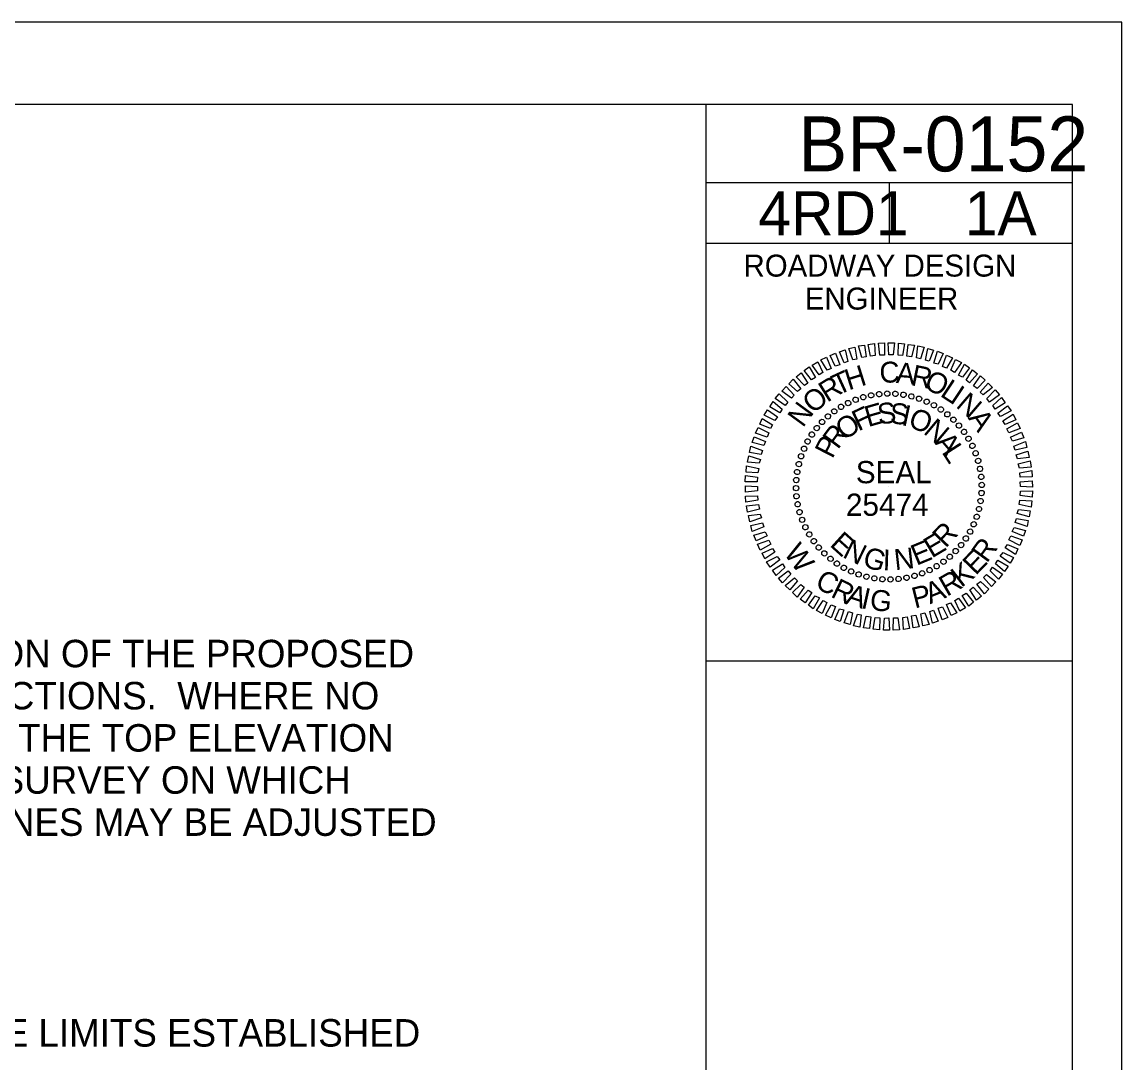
# Model space of a CAD drawing. Extents: x 1552903 to 1553045, y 811348 to 811440.
# Drawn here: x 1553019.79 to 1553044.82, y 811416.33 to 811440 of the extents above; entities that cross this region are included whole.
import ezdxf

# ---------------------------------------------------------------- set-up
doc = ezdxf.new("R2010")
doc.units = 0
for name, color, linetype in [('Default', 7, 'Continuous'), ('Prop Terminator CELL', 7, 'Continuous'), ('Sheet Data Field CELL', 7, 'Continuous'), ('Sheet Plan CELL', 7, 'Continuous'), ('Typical Grade Point Symbol CELL', 7, 'Continuous'), ('Typical Terminator CELL', 7, 'Continuous'), ('Typical Text General CELL', 7, 'Continuous'), ('z - Construction', 7, 'Continuous')]:
    doc.layers.add(name, color=color, linetype=linetype)

msp = doc.modelspace()

# ---------------------------------------------------------------- linework, layer by layer
at = {"layer": 'Prop Terminator CELL'}
for p, q in [((1553043.691, 811438.123), (1552906.191, 811438.123)), ((1553043.689, 811350.208), (1553043.691, 811438.123)), ((1553043.691, 811436.338), (1553035.358, 811436.338)), ((1553039.524, 811434.963), (1553039.524, 811436.338)), ((1553043.691, 811434.963), (1553035.358, 811434.963))]:
    msp.add_line(p, q, dxfattribs=at)
at = {"layer": 'Typical Grade Point Symbol CELL'}
for p, q in [((1553035.354, 811433.387), (1553035.354, 811433.387)), ((1553038.754, 811431.412), (1553038.754, 811431.412)), ((1553038.93, 811431.47), (1553038.93, 811431.47)), ((1553039.111, 811431.511), (1553039.111, 811431.511)), ((1553039.291, 811431.539), (1553039.291, 811431.539)), ((1553039.477, 811431.551), (1553039.477, 811431.551)), ((1553039.662, 811431.546), (1553039.662, 811431.546)), ((1553039.844, 811431.524), (1553039.844, 811431.524)), ((1553040.025, 811431.489), (1553040.025, 811431.489)), ((1553040.203, 811431.437), (1553040.203, 811431.437)), ((1553040.373, 811431.369), (1553040.373, 811431.369)), ((1553038.27, 811431.147), (1553038.27, 811431.147)), ((1553038.424, 811431.25), (1553038.424, 811431.25)), ((1553038.587, 811431.338), (1553038.587, 811431.338)), ((1553040.539, 811431.287), (1553040.539, 811431.287)), ((1553040.696, 811431.189), (1553040.696, 811431.189)), ((1553037.992, 811430.906), (1553037.992, 811430.906)), ((1553038.125, 811431.035), (1553038.125, 811431.035)), ((1553040.846, 811431.082), (1553040.846, 811431.082)), ((1553040.983, 811430.958), (1553040.983, 811430.958)), ((1553037.761, 811430.619), (1553037.761, 811430.619)), ((1553037.868, 811430.769), (1553037.868, 811430.769)), ((1553041.111, 811430.825), (1553041.111, 811430.825)), ((1553041.223, 811430.68), (1553041.223, 811430.68)), ((1553037.663, 811430.462), (1553037.663, 811430.462)), ((1553041.327, 811430.526), (1553041.327, 811430.526)), ((1553041.414, 811430.363), (1553041.414, 811430.363)), ((1553037.513, 811430.127), (1553037.513, 811430.127)), ((1553037.582, 811430.296), (1553037.582, 811430.296)), ((1553041.489, 811430.196), (1553041.489, 811430.196)), ((1553037.461, 811429.949), (1553037.461, 811429.949)), ((1553041.547, 811430.02), (1553041.547, 811430.02)), ((1553037.427, 811429.767), (1553037.427, 811429.767)), ((1553041.588, 811429.84), (1553041.588, 811429.84)), ((1553041.616, 811429.659), (1553041.616, 811429.659)), ((1553037.399, 811429.4), (1553037.399, 811429.4)), ((1553037.404, 811429.585), (1553037.404, 811429.585)), ((1553039.514, 811429.437), (1553039.514, 811429.437)), ((1553041.628, 811429.474), (1553041.628, 811429.474)), ((1553037.411, 811429.215), (1553037.411, 811429.215)), ((1553041.623, 811429.288), (1553041.623, 811429.288)), ((1553037.439, 811429.034), (1553037.439, 811429.034)), ((1553041.566, 811428.925), (1553041.566, 811428.925)), ((1553041.601, 811429.107), (1553041.601, 811429.107)), ((1553037.48, 811428.854), (1553037.48, 811428.854)), ((1553037.538, 811428.678), (1553037.538, 811428.678)), ((1553041.514, 811428.747), (1553041.514, 811428.747)), ((1553037.613, 811428.51), (1553037.613, 811428.51)), ((1553041.364, 811428.412), (1553041.364, 811428.412)), ((1553041.445, 811428.577), (1553041.445, 811428.577)), ((1553037.7, 811428.348), (1553037.7, 811428.348)), ((1553037.804, 811428.194), (1553037.804, 811428.194)), ((1553041.266, 811428.254), (1553041.266, 811428.254)), ((1553037.916, 811428.048), (1553037.916, 811428.048)), ((1553038.044, 811427.916), (1553038.044, 811427.916)), ((1553041.035, 811427.968), (1553041.035, 811427.968)), ((1553041.159, 811428.105), (1553041.159, 811428.105)), ((1553038.181, 811427.791), (1553038.181, 811427.791)), ((1553038.331, 811427.685), (1553038.331, 811427.685)), ((1553040.603, 811427.623), (1553040.603, 811427.623)), ((1553040.757, 811427.727), (1553040.757, 811427.727)), ((1553040.902, 811427.839), (1553040.902, 811427.839)), ((1553038.488, 811427.586), (1553038.488, 811427.586)), ((1553038.654, 811427.505), (1553038.654, 811427.505)), ((1553038.824, 811427.436), (1553038.824, 811427.436)), ((1553039.002, 811427.384), (1553039.002, 811427.384)), ((1553039.916, 811427.363), (1553039.916, 811427.363)), ((1553040.097, 811427.404), (1553040.097, 811427.404)), ((1553040.273, 811427.462), (1553040.273, 811427.462)), ((1553040.44, 811427.536), (1553040.44, 811427.536)), ((1553039.183, 811427.35), (1553039.183, 811427.35)), ((1553039.365, 811427.328), (1553039.365, 811427.328)), ((1553039.55, 811427.322), (1553039.55, 811427.322)), ((1553039.736, 811427.334), (1553039.736, 811427.334)), ((1553043.691, 811425.463), (1553043.691, 811425.463))]:
    msp.add_line(p, q, dxfattribs=at)
for points in [[(1553038.898, 811432.367), (1553038.822, 811432.631), (1553038.96, 811432.65), (1553038.999, 811432.381)], [(1553039.099, 811432.4), (1553039.044, 811432.664), (1553039.183, 811432.688), (1553039.2, 811432.414)], [(1553039.31, 811432.424), (1553039.275, 811432.698), (1553039.414, 811432.7), (1553039.411, 811432.426)], [(1553039.512, 811432.428), (1553039.499, 811432.702), (1553039.638, 811432.704), (1553039.613, 811432.43)], [(1553039.723, 811432.423), (1553039.73, 811432.697), (1553039.87, 811432.679), (1553039.824, 811432.412)], [(1553039.925, 811432.397), (1553039.954, 811432.667), (1553040.094, 811432.653), (1553040.027, 811432.386)], [(1553040.141, 811432.359), (1553040.174, 811432.633), (1553040.318, 811432.606), (1553040.23, 811432.339)], [(1553038.111, 811432.079), (1553037.968, 811432.313), (1553038.097, 811432.374), (1553038.203, 811432.123)], [(1553038.294, 811432.175), (1553038.177, 811432.417), (1553038.298, 811432.47), (1553038.395, 811432.206)], [(1553038.495, 811432.25), (1553038.39, 811432.501), (1553038.52, 811432.541), (1553038.583, 811432.281)], [(1553038.697, 811432.313), (1553038.599, 811432.576), (1553038.742, 811432.608), (1553038.785, 811432.335)], [(1553040.344, 811432.312), (1553040.398, 811432.574), (1553040.529, 811432.538), (1553040.433, 811432.284)], [(1553040.535, 811432.244), (1553040.623, 811432.511), (1553040.746, 811432.462), (1553040.636, 811432.216)], [(1553040.73, 811432.167), (1553040.826, 811432.421), (1553040.958, 811432.365), (1553040.823, 811432.126)], [(1553037.752, 811431.862), (1553037.589, 811432.07), (1553037.697, 811432.156), (1553037.844, 811431.914)], [(1553037.931, 811431.975), (1553037.767, 811432.195), (1553037.897, 811432.269), (1553038.011, 811432.027)], [(1553040.925, 811432.078), (1553041.03, 811432.324), (1553041.162, 811432.255), (1553041.006, 811432.029)], [(1553041.096, 811431.971), (1553041.234, 811432.218), (1553041.345, 811432.136), (1553041.189, 811431.922)], [(1553037.433, 811431.595), (1553037.24, 811431.773), (1553037.339, 811431.876), (1553037.512, 811431.656)], [(1553037.594, 811431.729), (1553037.406, 811431.928), (1553037.518, 811432.018), (1553037.673, 811431.789)], [(1553041.27, 811431.852), (1553041.418, 811432.086), (1553041.533, 811432), (1553041.351, 811431.795)], [(1553041.437, 811431.724), (1553041.601, 811431.95), (1553041.704, 811431.851), (1553041.518, 811431.667)], [(1553037.296, 811431.441), (1553037.078, 811431.606), (1553037.178, 811431.709), (1553037.362, 811431.51)], [(1553041.591, 811431.584), (1553041.769, 811431.789), (1553041.871, 811431.69), (1553041.659, 811431.518)], [(1553041.745, 811431.435), (1553041.931, 811431.632), (1553042.026, 811431.524), (1553041.806, 811431.356)], [(1553037.036, 811431.112), (1553036.802, 811431.247), (1553036.88, 811431.371), (1553037.086, 811431.193)], [(1553037.156, 811431.275), (1553036.93, 811431.435), (1553037.02, 811431.546), (1553037.213, 811431.356)], [(1553041.879, 811431.277), (1553042.078, 811431.462), (1553042.16, 811431.341), (1553041.931, 811431.198)], [(1553036.917, 811430.938), (1553036.675, 811431.056), (1553036.753, 811431.179), (1553036.979, 811431.019)], [(1553041.991, 811431.106), (1553042.212, 811431.274), (1553042.294, 811431.154), (1553042.056, 811431.027)], [(1553036.819, 811430.755), (1553036.578, 811430.852), (1553036.634, 811430.983), (1553036.869, 811430.836)], [(1553042.108, 811430.927), (1553042.337, 811431.083), (1553042.398, 811430.953), (1553042.16, 811430.848)], [(1553042.2, 811430.748), (1553042.442, 811430.882), (1553042.503, 811430.753), (1553042.243, 811430.656)], [(1553036.743, 811430.56), (1553036.48, 811430.648), (1553036.537, 811430.779), (1553036.783, 811430.653)], [(1553042.283, 811430.555), (1553042.534, 811430.673), (1553042.587, 811430.544), (1553042.327, 811430.468)], [(1553036.666, 811430.369), (1553036.404, 811430.436), (1553036.452, 811430.567), (1553036.707, 811430.458)], [(1553042.358, 811430.354), (1553042.622, 811430.46), (1553042.654, 811430.322), (1553042.389, 811430.266)], [(1553036.564, 811429.963), (1553036.298, 811429.987), (1553036.325, 811430.131), (1553036.592, 811430.051)], [(1553036.611, 811430.166), (1553036.344, 811430.211), (1553036.371, 811430.351), (1553036.639, 811430.254)], [(1553042.412, 811430.153), (1553042.676, 811430.242), (1553042.708, 811430.099), (1553042.443, 811430.065)], [(1553036.534, 811429.747), (1553036.264, 811429.763), (1553036.278, 811429.907), (1553036.553, 811429.849)], [(1553042.458, 811429.952), (1553042.73, 811430.02), (1553042.75, 811429.877), (1553042.481, 811429.851)], [(1553036.52, 811429.545), (1553036.247, 811429.54), (1553036.253, 811429.683), (1553036.527, 811429.646)], [(1553042.491, 811429.75), (1553042.764, 811429.797), (1553042.775, 811429.654), (1553042.501, 811429.649)], [(1553036.524, 811429.334), (1553036.251, 811429.308), (1553036.248, 811429.451), (1553036.522, 811429.435)], [(1553042.503, 811429.54), (1553042.776, 811429.565), (1553042.779, 811429.422), (1553042.505, 811429.438)], [(1553036.536, 811429.124), (1553036.263, 811429.077), (1553036.252, 811429.22), (1553036.526, 811429.225)], [(1553042.493, 811429.126), (1553042.763, 811429.11), (1553042.749, 811428.967), (1553042.474, 811429.025)], [(1553042.507, 811429.329), (1553042.78, 811429.334), (1553042.774, 811429.19), (1553042.5, 811429.228)], [(1553036.569, 811428.922), (1553036.297, 811428.854), (1553036.277, 811428.997), (1553036.546, 811429.023)], [(1553042.463, 811428.911), (1553042.729, 811428.886), (1553042.702, 811428.743), (1553042.435, 811428.822)], [(1553036.615, 811428.721), (1553036.351, 811428.632), (1553036.319, 811428.774), (1553036.584, 811428.808)], [(1553036.669, 811428.519), (1553036.405, 811428.414), (1553036.373, 811428.552), (1553036.638, 811428.607)], [(1553042.416, 811428.708), (1553042.683, 811428.662), (1553042.656, 811428.523), (1553042.388, 811428.619)], [(1553036.744, 811428.318), (1553036.493, 811428.2), (1553036.44, 811428.33), (1553036.7, 811428.406)], [(1553042.361, 811428.505), (1553042.623, 811428.438), (1553042.575, 811428.306), (1553042.32, 811428.416)], [(1553036.827, 811428.126), (1553036.585, 811427.991), (1553036.524, 811428.121), (1553036.784, 811428.218)], [(1553042.208, 811428.119), (1553042.449, 811428.022), (1553042.393, 811427.89), (1553042.158, 811428.038)], [(1553042.284, 811428.314), (1553042.547, 811428.226), (1553042.49, 811428.094), (1553042.244, 811428.221)], [(1553036.919, 811427.946), (1553036.69, 811427.791), (1553036.629, 811427.92), (1553036.867, 811428.026)], [(1553042.11, 811427.936), (1553042.352, 811427.818), (1553042.274, 811427.694), (1553042.048, 811427.855)], [(1553037.036, 811427.767), (1553036.816, 811427.599), (1553036.733, 811427.72), (1553036.971, 811427.846)], [(1553037.148, 811427.597), (1553036.949, 811427.412), (1553036.867, 811427.533), (1553037.096, 811427.676)], [(1553041.991, 811427.761), (1553042.225, 811427.626), (1553042.147, 811427.503), (1553041.941, 811427.68)], [(1553037.282, 811427.439), (1553037.096, 811427.242), (1553037.001, 811427.35), (1553037.221, 811427.518)], [(1553037.436, 811427.29), (1553037.258, 811427.084), (1553037.156, 811427.184), (1553037.367, 811427.356)], [(1553041.731, 811427.432), (1553041.949, 811427.267), (1553041.849, 811427.165), (1553041.665, 811427.364)], [(1553041.871, 811427.599), (1553042.097, 811427.439), (1553042.006, 811427.327), (1553041.814, 811427.518)], [(1553037.59, 811427.149), (1553037.426, 811426.923), (1553037.323, 811427.022), (1553037.509, 811427.207)], [(1553041.432, 811427.145), (1553041.621, 811426.946), (1553041.509, 811426.855), (1553041.354, 811427.084)], [(1553041.595, 811427.278), (1553041.787, 811427.1), (1553041.688, 811426.997), (1553041.515, 811427.218)], [(1553037.757, 811427.022), (1553037.609, 811426.787), (1553037.494, 811426.874), (1553037.676, 811427.079)], [(1553037.932, 811426.902), (1553037.793, 811426.656), (1553037.682, 811426.738), (1553037.838, 811426.951)], [(1553041.095, 811426.899), (1553041.26, 811426.678), (1553041.13, 811426.604), (1553041.016, 811426.847)], [(1553041.275, 811427.011), (1553041.438, 811426.804), (1553041.33, 811426.717), (1553041.183, 811426.959)], [(1553038.102, 811426.796), (1553037.997, 811426.55), (1553037.865, 811426.619), (1553038.021, 811426.845)], [(1553038.297, 811426.707), (1553038.201, 811426.452), (1553038.069, 811426.509), (1553038.204, 811426.747)], [(1553038.492, 811426.63), (1553038.404, 811426.363), (1553038.281, 811426.411), (1553038.391, 811426.658)], [(1553040.532, 811426.623), (1553040.637, 811426.372), (1553040.507, 811426.332), (1553040.444, 811426.592)], [(1553040.733, 811426.698), (1553040.851, 811426.456), (1553040.729, 811426.404), (1553040.632, 811426.667)], [(1553040.916, 811426.794), (1553041.059, 811426.561), (1553040.93, 811426.5), (1553040.824, 811426.751)], [(1553038.683, 811426.562), (1553038.629, 811426.299), (1553038.497, 811426.335), (1553038.594, 811426.59)], [(1553038.886, 811426.515), (1553038.853, 811426.24), (1553038.709, 811426.267), (1553038.797, 811426.534)], [(1553039.102, 811426.476), (1553039.073, 811426.206), (1553038.933, 811426.221), (1553039, 811426.487)], [(1553039.304, 811426.45), (1553039.297, 811426.176), (1553039.157, 811426.195), (1553039.203, 811426.461)], [(1553039.515, 811426.446), (1553039.528, 811426.172), (1553039.389, 811426.17), (1553039.414, 811426.444)], [(1553039.717, 811426.449), (1553039.752, 811426.176), (1553039.613, 811426.173), (1553039.616, 811426.447)], [(1553039.928, 811426.474), (1553039.983, 811426.209), (1553039.844, 811426.186), (1553039.827, 811426.459)], [(1553040.129, 811426.507), (1553040.205, 811426.243), (1553040.067, 811426.223), (1553040.028, 811426.492)], [(1553040.33, 811426.561), (1553040.428, 811426.297), (1553040.285, 811426.265), (1553040.242, 811426.538)]]:
    msp.add_lwpolyline(points, close=True, dxfattribs=at)
for centre, major_axis in [((1553038.587, 811431.334), (-0.0266, 0.0545)), ((1553038.756, 811431.408), (-0.0217, 0.0566)), ((1553038.931, 811431.466), (-0.0167, 0.0583)), ((1553039.11, 811431.509), (-0.0116, 0.0595)), ((1553039.292, 811431.536), (-0.0063, 0.0603)), ((1553039.476, 811431.548), (-0.0011, 0.0606)), ((1553039.661, 811431.543), (0.0042, 0.0605)), ((1553039.844, 811431.522), (0.0095, 0.0599)), ((1553040.024, 811431.485), (0.0147, 0.0589)), ((1553040.201, 811431.433), (0.0197, 0.0574)), ((1553040.373, 811431.365), (0.0247, 0.0554)), ((1553038.271, 811431.145), (-0.0357, 0.0491)), ((1553038.425, 811431.246), (-0.0312, 0.052)), ((1553040.538, 811431.283), (0.0294, 0.0531)), ((1553040.695, 811431.187), (0.0339, 0.0503)), ((1553040.843, 811431.077), (0.0382, 0.0471)), ((1553037.993, 811430.903), (-0.0436, 0.0421)), ((1553038.127, 811431.03), (-0.0398, 0.0458)), ((1553040.981, 811430.955), (0.0421, 0.0436)), ((1553041.108, 811430.821), (0.0458, 0.0398)), ((1553037.762, 811430.617), (-0.0503, 0.0339)), ((1553037.871, 811430.765), (-0.0471, 0.0382)), ((1553041.223, 811430.677), (0.0491, 0.0357)), ((1553037.583, 811430.295), (-0.0554, 0.0247)), ((1553037.665, 811430.459), (-0.0531, 0.0294)), ((1553041.324, 811430.523), (0.052, 0.0312)), ((1553041.412, 811430.361), (0.0545, 0.0266)), ((1553037.515, 811430.123), (-0.0574, 0.0197)), ((1553041.486, 811430.192), (0.0566, 0.0217)), ((1553037.463, 811429.946), (-0.0589, 0.0147)), ((1553041.544, 811430.018), (0.0583, 0.0167)), ((1553041.587, 811429.838), (0.0595, 0.0116)), ((1553037.405, 811429.583), (-0.0605, 0.0042)), ((1553037.426, 811429.766), (-0.0599, 0.0095)), ((1553041.615, 811429.656), (0.0603, 0.0063)), ((1553037.401, 811429.398), (-0.0606, -0.0011)), ((1553041.626, 811429.472), (0.0606, 0.0011)), ((1553037.412, 811429.214), (-0.0603, -0.0063)), ((1553041.6, 811429.105), (0.0599, -0.0095)), ((1553041.621, 811429.288), (0.0605, -0.0042)), ((1553037.439, 811429.032), (-0.0595, -0.0116)), ((1553037.482, 811428.853), (-0.0583, -0.0167)), ((1553041.563, 811428.924), (0.0589, -0.0147)), ((1553037.541, 811428.678), (-0.0566, -0.0217)), ((1553041.443, 811428.576), (0.0554, -0.0247)), ((1553041.511, 811428.747), (0.0574, -0.0197)), ((1553037.614, 811428.509), (-0.0545, -0.0266)), ((1553037.702, 811428.347), (-0.052, -0.0312)), ((1553041.361, 811428.411), (0.0531, -0.0294)), ((1553037.804, 811428.193), (-0.0491, -0.0357)), ((1553037.919, 811428.049), (-0.0458, -0.0398)), ((1553041.155, 811428.105), (0.0471, -0.0382)), ((1553041.265, 811428.254), (0.0503, -0.0339)), ((1553038.045, 811427.915), (-0.0421, -0.0436)), ((1553038.184, 811427.793), (-0.0382, -0.0471)), ((1553040.899, 811427.84), (0.0398, -0.0458)), ((1553041.033, 811427.967), (0.0436, -0.0421)), ((1553038.332, 811427.683), (-0.0339, -0.0503)), ((1553038.489, 811427.587), (-0.0294, -0.0531)), ((1553040.601, 811427.624), (0.0312, -0.052)), ((1553040.755, 811427.726), (0.0357, -0.0491)), ((1553038.654, 811427.505), (-0.0247, -0.0554)), ((1553038.825, 811427.437), (-0.0197, -0.0574)), ((1553039.002, 811427.385), (-0.0147, -0.0589)), ((1553039.183, 811427.348), (-0.0095, -0.0599)), ((1553039.366, 811427.327), (-0.0042, -0.0605)), ((1553039.55, 811427.323), (0.0011, -0.0606)), ((1553039.734, 811427.334), (0.0063, -0.0603)), ((1553039.916, 811427.361), (0.0116, -0.0595)), ((1553040.096, 811427.404), (0.0167, -0.0583)), ((1553040.27, 811427.463), (0.0217, -0.0566)), ((1553040.439, 811427.536), (0.0266, -0.0545))]:
    msp.add_ellipse(centre, major_axis=major_axis, ratio=0.999708, dxfattribs=at)
at = {"layer": 'Typical Terminator CELL'}
for p, q in [((1553044.816, 811439.998), (1552903.151, 811439.998)), ((1553044.816, 811348.333), (1553044.816, 811439.998))]:
    msp.add_line(p, q, dxfattribs=at)
at = {"layer": 'z - Construction'}
for p, q in [((1553035.356, 811350.208), (1553035.358, 811438.123)), ((1553043.691, 811425.463), (1553035.358, 811425.463))]:
    msp.add_line(p, q, dxfattribs=at)

# ---------------------------------------------------------------- texts
at = {"layer": 'Default'}
msp.add_text('1A', height=1, dxfattribs=at).set_placement((1553041.239, 811435.151))
at = {"layer": 'Sheet Data Field CELL'}
for s, p in [('ROADWAY DESIGN', (1553036.207, 811434.209)), ('ENGINEER', (1553037.6, 811433.459))]:
    msp.add_text(s, height=0.5, dxfattribs=at).set_placement(p)
at = {"layer": 'Sheet Plan CELL'}
for s, p in [('         THE GRADE LINES SHOWN DENOTE THE FINISHED ELEVATION OF THE PROPOSED ', (1552992.723, 811425.325)), ('         SURFACING AT GRADE POINTS SHOWN ON THE TYPICAL SECTIONS.  WHERE NO ', (1552992.723, 811424.367)), ('         GRADE LINES ARE SHOWN, THE PROFILES SHOWN DENOTE THE TOP ELEVATION', (1552992.723, 811423.408)), ('         OF THE EXISTING PAVEMENT ALONG THE CENTER LINE OF SURVEY ON WHICH ', (1552992.723, 811422.45)), ('         THE PROPOSED RESURFACING WILL BE PLACED.  GRADE LINES MAY BE ADJUSTED ', (1552992.723, 811421.492)), ('         CLEARING ON THIS PROJECT SHALL BE PERFORMED TO THE LIMITS ESTABLISHED', (1552992.723, 811416.7))]:
    msp.add_text(s, height=0.625, dxfattribs=at).set_placement(p)
at = {"layer": 'Typical Grade Point Symbol CELL'}
for s, height, rotation, p in [('H', 0.475, 17.4535, (1553038.599, 811431.621)), ('C', 0.475, 2.9171, (1553039.311, 811431.787)), ('A', 0.475, 355.649, (1553039.666, 811431.79)), ('R', 0.475, 348.3808, (1553039.995, 811431.745)), ('R', 0.475, 31.9898, (1553038.109, 811431.339)), ('T', 0.475, 24.7216, (1553038.354, 811431.499)), ('O', 0.475, 333.8445, (1553040.284, 811431.685)), ('L', 0.475, 326.5763, (1553040.658, 811431.506)), ('O', 0.475, 39.2579, (1553037.791, 811431.074)), ('I', 0.475, 326.5763, (1553040.872, 811431.365)), ('N', 0.475, 53.7943, (1553037.559, 811430.758)), ('N', 0.475, 319.3082, (1553041.017, 811431.254)), ('F', 0.475, 25.3292, (1553038.819, 811430.685)), ('E', 0.475, 15.9853, (1553039.041, 811430.784)), ('S', 0.475, 6.6414, (1553039.28, 811430.844)), ('S', 0.475, 357.2975, (1553039.531, 811430.862)), ('I', 0.475, 347.9535, (1553039.782, 811430.836)), ('O', 0.475, 338.6096, (1553039.927, 811430.805)), ('A', 0.475, 304.7718, (1553041.305, 811430.99)), ('O', 0.475, 34.6731, (1553038.506, 811430.472)), ('N', 0.475, 319.9218, (1553040.277, 811430.657)), ('R', 0.475, 53.361, (1553038.351, 811430.262)), ('P', 0.475, 62.7049, (1553038.227, 811430.05)), ('A', 0.475, 310.5779, (1553040.544, 811430.424)), ('L', 0.475, 302.7465, (1553040.704, 811430.22)), ('SEAL', 0.5053, 0, (1553038.761, 811429.51)), ('25474', 0.5055, 0, (1553038.536, 811428.769)), ('E', 0.475, 317.8985, (1553038.148, 811428.097)), ('E', 0.475, 30.5764, (1553040.489, 811427.796)), ('R', 0.475, 46.7271, (1553040.803, 811428.021)), ('W', 0.475, 305.9992, (1553037.109, 811427.921)), ('N', 0.475, 334.0491, (1553038.438, 811427.837)), ('E', 0.475, 22.5011, (1553040.14, 811427.63)), ('R', 0.475, 54, (1553041.741, 811427.678)), ('G', 0.475, 342.1244, (1553038.888, 811427.633)), ('I', 0.475, 358.2751, (1553039.369, 811427.531)), ('N', 0.475, 6.3504, (1553039.658, 811427.532)), ('E', 0.475, 46, (1553041.487, 811427.398)), ('.', 0.475, 310.4999, (1553037.329, 811427.627)), ('K', 0.475, 38, (1553041.161, 811427.125)), ('C', 0.475, 334, (1553037.809, 811427.143)), ('R', 0.475, 30, (1553040.833, 811426.924)), ('R', 0.475, 334, (1553038.168, 811426.937)), ('A', 0.475, 342, (1553038.509, 811426.781)), ('I', 0.475, 347.5, (1553038.861, 811426.676)), ('P', 0.475, 14, (1553040.102, 811426.66)), ('A', 0.475, 22, (1553040.451, 811426.757)), ('G', 0.475, 354, (1553039.066, 811426.632))]:
    msp.add_text(s, height=height, rotation=rotation, dxfattribs=at).set_placement(p)
at = {"layer": 'Typical Text General CELL'}
for s, height, p in [('BR-0152', 1.25, (1553037.451, 811436.601)), ('4RD1', 1, (1553036.545, 811435.151))]:
    msp.add_text(s, height=height, dxfattribs=at).set_placement(p)

doc.saveas('drawing.dxf')
